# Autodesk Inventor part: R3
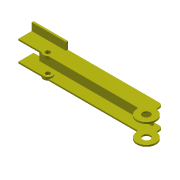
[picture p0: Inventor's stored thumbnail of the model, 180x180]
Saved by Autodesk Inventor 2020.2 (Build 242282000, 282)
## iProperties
Created: 2005-10
Part Number: R3
Document SubType Name: Modeling
Designer: F.Stasiak
Density: 1 g/cm^3
Material: Ogólny
Appearance: Żółta
Manager: www.cadconsulting.pl
Company: Fabian Stasiak CAD Consulting
Author: F.Stasiak
Subject: Zbiór ćwiczeń. Autodesk Inventor 2020. Kurs podstawowy
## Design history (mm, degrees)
sketch "Szkic1"
  geometry: L1 (-315.036, 943.824)-(-2015.036, 943.824); L2 (-2015.036, 943.824)-(-2015.036, 1143.824); L3 (-2015.036, 1143.824)-(-315.036, 1143.824); L4 (-315.036, 943.824)-(-315.036, 1143.824)
  constraints: 8 end point, 2 perpendicular, 1 horizontal, 1 parallel
  dimensions: "d4" = 1700 distance of L1.start L1.end; "d5" = 200 distance of L1.start L3.end
extrude "Wyciągnięcie proste1" new body sketch "Szkic1" stored distance "d2" = 240; taper "d3" = 0 deg
feature "Skorupa1" dims "d6" = 20
sketch "Szkic2"
  geometry: L1 (2015.036, 943.824)-(315.036, 943.824) reference; L2 (315.036, 943.824)-(315.036, 1143.824) reference; C1 r 125 at (315.036, 923.824)
  constraints: 1 centre point
  dimensions: "d7" = 250 diameter of C1; "d8" = 20 distance from line of L1 C1.centre; "d9" = 0 distance from line of L2 C1.centre
extrude "Wyciągnięcie proste2" join sketch "Szkic2" distance "d10" = 20; taper "d11" = 0 deg
sketch "Szkic3"
  geometry: C1 r 50 at (1667.653, 983.824) reference; C2 r 60 at (1667.653, 983.824)
  constraints: 1 centre point, 1 coincident
  dimensions: "d12" = 120 diameter of C2
extrude "Wyciągnięcie proste3" join sketch "Szkic3" distance "d13" = 40; taper "d14" = 0 deg
sketch "Szkic4"
  geometry: L1 (0, 0)-(1700, 0) reference; L2 (1570, -55)-(90, -55); L3 (90, -55)-(90, -30); L4 (90, -30)-(1570, -30); L5 (1570, -30)-(1570, -55); L6 (1700, 0)-(1700, -200) reference
  constraints: 8 end point, 3 parallel, 1 horizontal, 1 perpendicular
  dimensions: "d15" = 30 distance between parallel lines of L1 L4; "d16" = 25 distance of L4.end L2.start; "d17" = 130 distance between parallel lines of L6 L5; "d18" = 1480 distance of L3.end L4.end
extrude "Wyciągnięcie proste4" join sketch "Szkic4" stored distance "d19" = 10; taper "d20" = 0 deg
fillet "Zaokrąglenie1" dims "d21" = 20
fillet "Zaokrąglenie2" dims "d22" = 50
sketch "Szkic7"
  geometry: L1 (365.036, 1143.824)-(2015.036, 1143.824) reference; L2 (2015.036, 1143.824)-(2015.036, 943.824) reference; L3 (2015.036, 1143.824)-(1565.036, 1143.824); L4 (1565.036, 1143.824)-(1565.036, 1118.824); L5 (1565.036, 1118.824)-(2015.036, 1118.824); L6 (2015.036, 1118.824)-(2015.036, 1143.824)
  constraints: 8 end point, 2 parallel, 1 horizontal, 1 perpendicular
  dimensions: "d37" = 25 distance of L3.end L4.end; "d38" = 450 distance of L4.end L5.end
extrude "Wyciągnięcie proste5" join sketch "Szkic7" distance "d39" = 100; taper "d40" = 0 deg
mirror "Lustro1"
sketch "Szkic5"
  geometry: A1 r 60 centre (1667.653, 983.824) between (1622.932, 943.824) and (1712.375, 943.824) reference
hole "Otwór1" sketch "Szkic5" at (1667.653, 983.824) diameter "d23" = 60; stored, may be unused: countersink angle "d27" = 90 deg, drill point angle "d29" = 118 deg; dims "d24" = 6, "d25" = 4, "d26" = 2, "d28" = 8
sketch "Szkic6"
  geometry: A1 r 125 centre (315.036, 923.824) between (297.795, 1047.629) and (440.036, 923.824) reference
hole "Otwór2" sketch "Szkic6" at (315.036, 923.824) diameter "d30" = 100; stored, may be unused: countersink angle "d34" = 90 deg, drill point angle "d36" = 118 deg; dims "d31" = 6, "d32" = 4, "d33" = 2, "d35" = 8
node "Bryła1"
node "Korpusy bryłowe"
node "Korpusy powierzchniowe"
node "Odniesienie1"
